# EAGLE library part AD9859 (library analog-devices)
CMOS Direct Digital Synthesizer 400 MSPS, 10-Bit, 1.8 V Source: www.analog.com/UploadedFiles/Data_Sheets/33830397585263AD9859_0.pdf
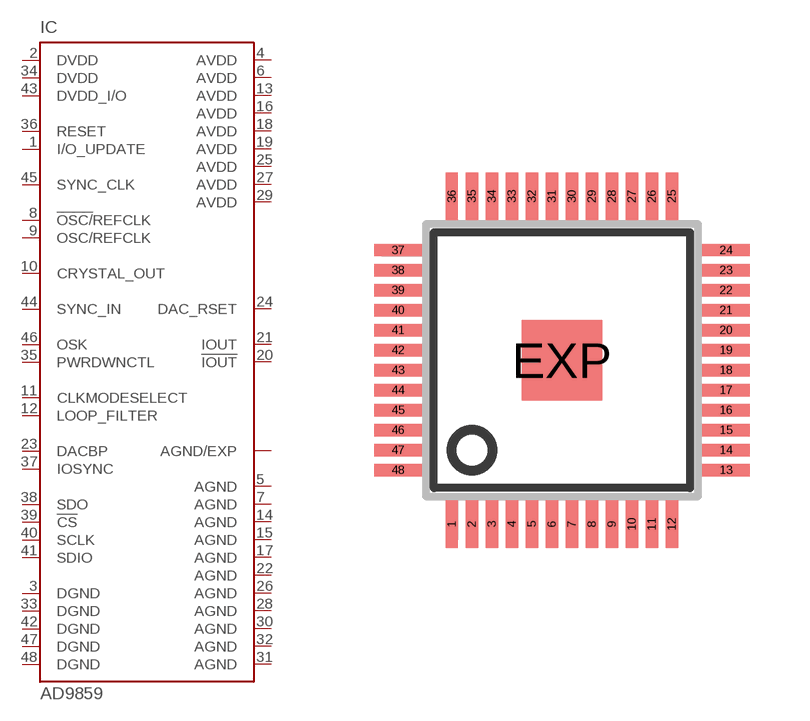
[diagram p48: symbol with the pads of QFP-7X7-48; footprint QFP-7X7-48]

Designator prefix IC

## AD9859 (MF: ALTERA CORPORATION; MPN: AD9859YSVZ; OC_FARNELL: 1438601; OC_NEWARK: 59K7492)  [QFP-7X7-48]
1  I/O_UPDATE  in
2  DVDD  in
3  DGND  in
4  AVDD  in
5  AGND  in
6  AVDD  in
7  AGND  in
8  !OSC/!REFCLK  in
9  OSC/REFCLK  in
10  CRYSTAL_OUT  out
11  CLKMODESELECT  in
12  LOOP_FILTER  in
13  AVDD  in
14  AGND  in
15  AGND  in
16  AVDD  in
17  AGND  in
18  AVDD  in
19  AVDD  in
20  !IOUT  out
21  IOUT  out
22  AGND  in
23  DACBP  in
24  DAC_RSET  in
25  AVDD  in
26  AGND  in
27  AVDD  in
28  AGND  in
29  AVDD  in
30  AGND  in
31  AGND  in
32  AGND  in
33  DGND  in
34  DVDD  in
35  PWRDWNCTL  in
36  RESET  in
37  IOSYNC  in
38  SDO  out
39  !CS  in
40  SCLK  in
41  SDIO
42  DGND  in
43  DVDD_I/O  in
44  SYNC_IN  in
45  SYNC_CLK  out
46  OSK  in
47  DGND  in
48  DGND  in
EXP  AGND/EXP  in

## Footprint QFP-7X7-48 (pad centres in mm)
TQFP48 7x7 Thin Plastic Quad Flat Package, Exposed Pad, TQFP/EP Source: www.analog.com/UploadedFiles/Data_Sheets/33830397585263AD9859_0.pdf
smd 0.3 x 1.2: 1 -2.75,-4.1; 2 -2.25,-4.1; 3 -1.75,-4.1; 4 -1.25,-4.1; 5 -0.75,-4.1; 6 -0.25,-4.1; 7 0.25,-4.1; 8 0.75,-4.1; 9 1.25,-4.1; 10 1.75,-4.1; 11 2.25,-4.1; 12 2.75,-4.1; 25 2.75,4.1; 26 2.25,4.1; 27 1.75,4.1; 28 1.25,4.1; 29 0.75,4.1; 30 0.25,4.1; 31 -0.25,4.1; 32 -0.75,4.1; 33 -1.25,4.1; 34 -1.75,4.1; 35 -2.25,4.1; 36 -2.75,4.1
smd 1.2 x 0.3: 13 4.1,-2.75; 14 4.1,-2.25; 15 4.1,-1.75; 16 4.1,-1.25; 17 4.1,-0.75; 18 4.1,-0.25; 19 4.1,0.25; 20 4.1,0.75; 21 4.1,1.25; 22 4.1,1.75; 23 4.1,2.25; 24 4.1,2.75; 37 -4.1,2.75; 38 -4.1,2.25; 39 -4.1,1.75; 40 -4.1,1.25; 41 -4.1,0.75; 42 -4.1,0.25; 43 -4.1,-0.25; 44 -4.1,-0.75; 45 -4.1,-1.25; 46 -4.1,-1.75; 47 -4.1,-2.25; 48 -4.1,-2.75
smd 2 x 2: EXP 0,0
